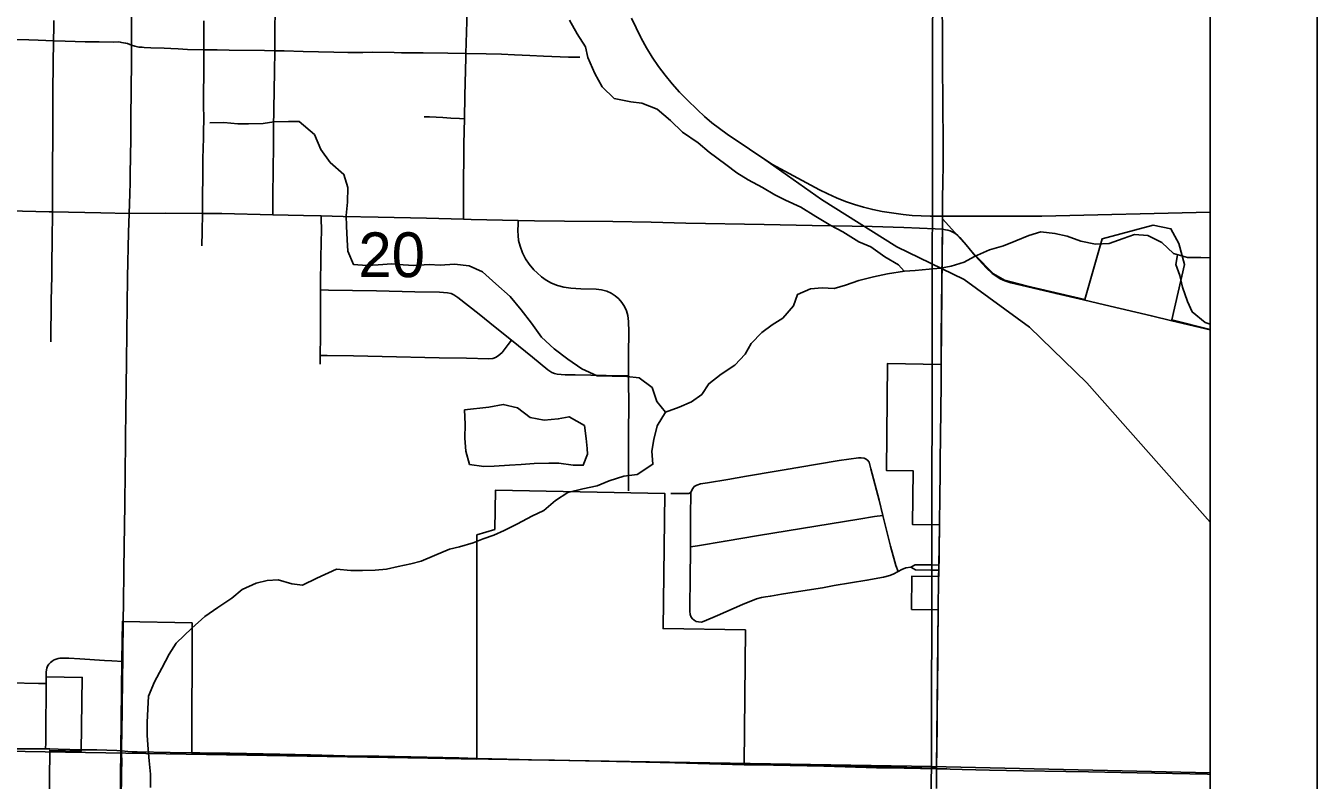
# Model space of a CAD drawing. Extents: x 0 to 34, y 0 to 22.
# Drawn here: x 7.793 to 9, y 18.41 to 19.115 of the extents above; entities that cross this region are included whole.
import ezdxf

# ---------------------------------------------------------------- set-up
doc = ezdxf.new("R2010")
doc.units = 0
for name, color, linetype in [('GM_X_City_Street', 7, 'Continuous'), ('GM_X_County_Road', 7, 'Continuous'), ('GM_X_County_Text', 7, 'Continuous'), ('GM_X_Minor_Lake', 7, 'Continuous'), ('GM_X_Minor_River', 7, 'Continuous'), ('GM_X_Rail_Line', 7, 'Continuous'), ('GM_X_Rail_Line_Text', 7, 'Continuous'), ('GM_X_Section', 7, 'Continuous'), ('GM_X_Section_Text', 7, 'Continuous'), ('GM_X_State_Route', 7, 'Continuous'), ('GM_X_Township_Road', 7, 'Continuous'), ('GM_X_US_Route', 7, 'Continuous'), ('SH_Cut_Line', 7, 'Continuous'), ('SH_Data', 7, 'Continuous')]:
    doc.layers.add(name, color=color, linetype=linetype)

msp = doc.modelspace()

# ---------------------------------------------------------------- linework, layer by layer
at = {"layer": 'GM_X_City_Street'}
for points in [[(8.0237, 18.9388), (8.0237, 18.9421), (8.0237, 18.9557), (8.024, 18.9818), (8.0242, 19.0022), (8.0244, 19.0201), (8.0253, 19.0728), (8.0254, 19.0922), (8.0254, 19.0969), (8.0256, 19.1112), (8.0259, 19.1303)], [(7.816, 18.8201), (7.8165, 18.859), (7.8169, 18.881), (7.817, 18.8932), (7.8174, 18.9149), (7.8175, 18.9415), (7.8175, 18.9544), (7.8177, 18.9892), (7.8178, 19.0065), (7.8178, 19.0187), (7.8179, 19.034), (7.8179, 19.0408), (7.8179, 19.0569), (7.8181, 19.0643), (7.8182, 19.0696), (7.8183, 19.0819), (7.8186, 19.0996), (7.8186, 19.1016), (7.8188, 19.1143), (7.8189, 19.1204)], [(7.9573, 18.9098), (7.9576, 18.9231), (7.958, 18.9401), (7.9582, 18.9909), (7.9585, 19.0014), (7.9587, 19.0101), (7.9588, 19.0113), (7.9588, 19.0151), (7.9589, 19.0181), (7.9591, 19.0268), (7.9589, 19.0436), (7.9588, 19.0479), (7.9588, 19.0522), (7.9589, 19.0552), (7.9589, 19.0583), (7.9591, 19.0645), (7.9591, 19.0695), (7.9592, 19.08), (7.9591, 19.09), (7.9591, 19.0924), (7.9591, 19.0931), (7.9591, 19.0974), (7.9591, 19.106), (7.9591, 19.1084), (7.9591, 19.1202)], [(7.7744, 19.1026), (7.7955, 19.1023), (7.8042, 19.1021), (7.8186, 19.1016), (7.8296, 19.1012), (7.8481, 19.1004), (7.8612, 19.1004), (7.8742, 19.1003), (7.8792, 19.1004), (7.8809, 19.1003), (7.8822, 19.1), (7.8839, 19.0997), (7.886, 19.0993), (7.8878, 19.0988), (7.8916, 19.0975)], [(7.8916, 19.0975), (7.8947, 19.0966), (7.897, 19.0959), (7.8985, 19.0956), (7.8998, 19.0954), (7.9014, 19.0954), (7.9032, 19.0953), (7.9097, 19.095), (7.9219, 19.0946), (7.9284, 19.0942), (7.935, 19.0939), (7.9439, 19.0935), (7.9591, 19.0931), (7.9618, 19.093), (7.9717, 19.093), (7.9828, 19.0928), (8.0157, 19.0924), (8.0254, 19.0922), (8.0342, 19.0921), (8.0521, 19.0915), (8.0806, 19.0907), (8.0936, 19.0906), (8.1079, 19.0906), (8.1172, 19.0907), (8.137, 19.0904), (8.1438, 19.0903), (8.1568, 19.0902), (8.1643, 19.0901), (8.1872, 19.09), (8.2041, 19.0897), (8.2231, 19.0893), (8.2373, 19.089), (8.2496, 19.0883), (8.2638, 19.0878), (8.2768, 19.0872), (8.2922, 19.0866), (8.3, 19.0862), (8.3027, 19.0861), (8.3108, 19.0862)], [(8.165, 19.0305), (8.1702, 19.0303), (8.1827, 19.0297), (8.1901, 19.0292), (8.1981, 19.0288), (8.2027, 19.0286)], [(8.0679, 18.7992), (8.068, 18.8074), (8.0681, 18.8252), (8.0682, 18.8686), (8.0682, 18.8731), (8.0685, 18.8993), (8.069, 18.9254), (8.0689, 18.9343), (8.0689, 18.9377)], [(8.3563, 18.6806), (8.3563, 18.6917), (8.3562, 18.7265), (8.3563, 18.7395), (8.3564, 18.7569), (8.3562, 18.7883), (8.3562, 18.7917), (8.3563, 18.8084), (8.3564, 18.8295), (8.3563, 18.8389), (8.3555, 18.8446), (8.3543, 18.8489), (8.3524, 18.853), (8.35, 18.8568), (8.347, 18.8602), (8.3437, 18.8632), (8.3399, 18.8656), (8.3358, 18.8674), (8.3309, 18.8686), (8.3258, 18.8692), (8.3115, 18.8696), (8.3023, 18.8701), (8.2957, 18.8712), (8.2898, 18.8728), (8.2841, 18.875), (8.2793, 18.8776), (8.2748, 18.8808), (8.2707, 18.8844), (8.2676, 18.8874), (8.2634, 18.8926), (8.26, 18.8977), (8.2572, 18.9031), (8.2548, 18.9094), (8.2534, 18.9147), (8.2529, 18.9195), (8.2528, 18.9238), (8.253, 18.9305), (8.253, 18.9336)], [(8.0682, 18.8686), (8.0757, 18.8684), (8.1205, 18.8676), (8.1565, 18.8668), (8.1795, 18.8664), (8.1868, 18.8658), (8.1903, 18.8651), (8.193, 18.8639), (8.1965, 18.8616), (8.2164, 18.8458), (8.2314, 18.8338), (8.2467, 18.8215), (8.2663, 18.8058), (8.2808, 18.794), (8.2845, 18.7915), (8.2869, 18.7904), (8.2895, 18.7898), (8.297, 18.7893), (8.3064, 18.7892), (8.3498, 18.7884), (8.3562, 18.7883)], [(8.068, 18.8074), (8.0743, 18.8073), (8.0991, 18.8068), (8.1258, 18.8064), (8.1792, 18.8051), (8.2047, 18.8047), (8.2257, 18.8041), (8.2292, 18.8044), (8.2319, 18.8053), (8.2343, 18.8069), (8.2379, 18.8102), (8.2418, 18.8149), (8.2436, 18.8174), (8.2467, 18.8215)], [(8.3957, 18.6784), (8.4045, 18.6783), (8.4098, 18.6783), (8.4124, 18.6784), (8.4143, 18.6791), (8.4151, 18.6808), (8.4162, 18.6829), (8.4176, 18.6848), (8.4199, 18.6859), (8.4235, 18.6873), (8.43, 18.6882), (8.4489, 18.6914), (8.4666, 18.6946), (8.4942, 18.6992), (8.5053, 18.7011), (8.5145, 18.7024), (8.5532, 18.709), (8.5712, 18.7116), (8.5737, 18.7117), (8.5764, 18.7114), (8.5784, 18.7105)], [(8.6082, 18.6052), (8.6062, 18.6109), (8.605, 18.6143), (8.6011, 18.629), (8.594, 18.6577), (8.5905, 18.6719), (8.5826, 18.7014), (8.581, 18.7074), (8.5797, 18.7093), (8.5784, 18.7105)], [(8.4194, 18.5587), (8.4175, 18.5597), (8.4159, 18.5611), (8.4147, 18.5627), (8.4137, 18.5652), (8.4135, 18.5682), (8.4136, 18.5751), (8.4137, 18.5964), (8.414, 18.6283), (8.4142, 18.6599), (8.4145, 18.676), (8.4143, 18.6791)], [(8.414, 18.6283), (8.4206, 18.6294), (8.4464, 18.6337), (8.4777, 18.6389), (8.5715, 18.6544), (8.5862, 18.6566), (8.594, 18.6577)], [(8.4194, 18.5587), (8.4217, 18.5582), (8.4243, 18.5581), (8.4268, 18.5589), (8.4394, 18.5643), (8.4628, 18.5744), (8.4759, 18.5798), (8.4806, 18.5809), (8.4841, 18.5816), (8.4888, 18.5824), (8.4991, 18.5841), (8.5111, 18.5861), (8.5375, 18.5902), (8.5485, 18.5922), (8.5791, 18.5971), (8.5945, 18.5999), (8.6006, 18.6015), (8.6041, 18.603), (8.6075, 18.6049), (8.6082, 18.6052), (8.6118, 18.6072), (8.6153, 18.6086), (8.62, 18.6093)], [(8.62, 18.6093), (8.6243, 18.6116), (8.6255, 18.6117), (8.639, 18.6114), (8.6463, 18.6112)], [(8.62, 18.6093), (8.6244, 18.607), (8.6389, 18.6067), (8.6462, 18.6065)]]:
    msp.add_lwpolyline(points, dxfattribs=at)
at = {"layer": 'GM_X_County_Road'}
for p, q in [((8.6496, 18.9255), (8.6497, 18.9335)), ((8.864, 18.8398), (8.9, 18.8312)), ((8.6484, 18.7872), (8.6484, 18.7969)), ((8.6456, 18.5684), (8.6461, 18.5997))]:
    msp.add_line(p, q, dxfattribs=at)
for points in [[(8.2041, 19.0897), (8.2049, 19.1196), (8.2052, 19.1414), (8.2061, 19.1776)], [(8.6497, 18.9335), (8.6498, 18.9455), (8.6498, 18.9556), (8.6499, 18.9676), (8.6502, 18.9866), (8.6503, 19.0082), (8.65, 19.0399), (8.6499, 19.0548), (8.6498, 19.0679), (8.6497, 19.0896), (8.6496, 19.1108), (8.6494, 19.1319), (8.6491, 19.1605), (8.6491, 19.1611)], [(8.2027, 19.0286), (8.203, 19.05), (8.204, 19.086), (8.2041, 19.0897)], [(8.2019, 18.9347), (8.2019, 18.9371), (8.2019, 18.9414), (8.2018, 18.9468), (8.2019, 18.958), (8.2023, 19.0053), (8.2027, 19.0286)], [(7.7516, 18.9431), (7.8146, 18.9416), (7.8175, 18.9415)], [(7.8175, 18.9415), (7.8628, 18.9405), (7.8892, 18.94)], [(7.8892, 18.94), (7.9231, 18.9403), (7.958, 18.9401)], [(7.958, 18.9401), (7.976, 18.9399), (8.0237, 18.9388)], [(8.0237, 18.9388), (8.0522, 18.9381), (8.0689, 18.9377)], [(8.0689, 18.9377), (8.0895, 18.9371), (8.1221, 18.9365), (8.1672, 18.9356), (8.2019, 18.9347)], [(8.2019, 18.9347), (8.2092, 18.9345), (8.253, 18.9336)], [(8.253, 18.9336), (8.2683, 18.9333), (8.2963, 18.9327), (8.3414, 18.9325), (8.3772, 18.9318), (8.4098, 18.931), (8.4829, 18.9298), (8.528, 18.9288), (8.5653, 18.9281), (8.584, 18.9279), (8.6135, 18.9268), (8.6429, 18.9257), (8.6496, 18.9255)], [(8.6492, 18.8853), (8.6493, 18.8961), (8.6496, 18.9255)], [(8.6496, 18.9255), (8.6525, 18.9249), (8.6546, 18.9244), (8.657, 18.9237), (8.6587, 18.923), (8.6605, 18.922), (8.6622, 18.9209), (8.664, 18.9193), (8.6658, 18.9175), (8.6719, 18.9107), (8.6804, 18.9004)], [(8.6804, 18.9004), (8.6905, 18.8892), (8.6962, 18.884), (8.6998, 18.8813), (8.7037, 18.879), (8.7079, 18.8771), (8.7137, 18.8752), (8.7559, 18.8652), (8.7815, 18.8592)], [(8.6484, 18.7969), (8.6484, 18.7979), (8.6484, 18.8044), (8.6486, 18.8296), (8.6487, 18.8458), (8.6489, 18.8551), (8.6491, 18.8744), (8.6492, 18.8853)], [(8.7815, 18.8592), (8.8012, 18.8546), (8.845, 18.8442), (8.864, 18.8398)], [(8.6469, 18.647), (8.6469, 18.648), (8.6472, 18.6774), (8.6474, 18.6951), (8.6476, 18.7084), (8.6481, 18.7555), (8.6484, 18.7813), (8.6484, 18.7872)], [(8.6462, 18.6065), (8.6463, 18.6112), (8.6469, 18.647)], [(8.6461, 18.5997), (8.6461, 18.6021), (8.6462, 18.6065)], [(8.6441, 18.4208), (8.6444, 18.4408), (8.6446, 18.4595), (8.6446, 18.4713), (8.6453, 18.526), (8.6453, 18.5391), (8.6456, 18.5684)], [(8.6441, 18.4023), (8.6441, 18.4208)]]:
    msp.add_lwpolyline(points, dxfattribs=at)
at = {"layer": 'GM_X_County_Text'}
msp.add_lwpolyline([(8.9, 16.3981), (8.9, 20.9)], dxfattribs=at)
at = {"layer": 'GM_X_Minor_Lake'}
for points in [[(8.3174, 18.7203), (8.3166, 18.7296), (8.3149, 18.7418), (8.3006, 18.75), (8.2904, 18.7479), (8.2774, 18.7467), (8.2642, 18.7492), (8.2523, 18.7582), (8.2391, 18.7615), (8.2257, 18.7591), (8.2029, 18.7565)], [(8.2029, 18.7565), (8.2034, 18.7432), (8.2032, 18.7299), (8.2041, 18.7177), (8.2076, 18.7055), (8.2209, 18.7034), (8.2307, 18.7039), (8.2448, 18.7048), (8.2558, 18.7053), (8.2679, 18.7062), (8.2816, 18.7067), (8.2911, 18.7066), (8.3043, 18.7048), (8.3138, 18.7046), (8.3178, 18.7151), (8.3174, 18.7203)]]:
    msp.add_lwpolyline(points, dxfattribs=at)
at = {"layer": 'GM_X_Minor_River'}
for points in [[(8.6138, 18.8861), (8.6087, 18.892), (8.5959, 18.8995), (8.5828, 18.9088), (8.5715, 18.9136), (8.5565, 18.923), (8.5453, 18.9289), (8.5314, 18.9371), (8.5172, 18.9458), (8.5029, 18.9525), (8.4931, 18.9576), (8.4815, 18.9643), (8.468, 18.9714), (8.4575, 18.978), (8.447, 18.9858), (8.4317, 18.9975), (8.4213, 19.0061), (8.4067, 19.0162), (8.3955, 19.0271), (8.3828, 19.0376), (8.3685, 19.0431), (8.3583, 19.0445), (8.3428, 19.0474), (8.3316, 19.0583), (8.3247, 19.0709), (8.3181, 19.0859), (8.316, 19.0958), (8.3083, 19.1081), (8.301, 19.1207)], [(8.3906, 18.7543), (8.3825, 18.7643), (8.3782, 18.7773), (8.3662, 18.7863), (8.3545, 18.7877), (8.3268, 18.7882), (8.3125, 18.7949), (8.2994, 18.8039), (8.2867, 18.8136), (8.2748, 18.8245), (8.2656, 18.8376), (8.2559, 18.8499), (8.2456, 18.8623), (8.2321, 18.8743), (8.2198, 18.8855), (8.2071, 18.8911), (8.1934, 18.8925), (8.1801, 18.8916), (8.1699, 18.8922), (8.1555, 18.8913), (8.1456, 18.8919), (8.135, 18.8929), (8.1221, 18.892), (8.1115, 18.8914), (8.099, 18.8924), (8.0939, 18.9047), (8.093, 18.9153), (8.0925, 18.9282), (8.0923, 18.9381), (8.0933, 18.9506), (8.0939, 18.9643), (8.09, 18.9765), (8.0773, 18.9877), (8.0685, 18.9997), (8.0627, 19.0138), (8.0481, 19.0259), (8.0383, 19.0261), (8.0246, 19.0256), (8.0147, 19.0242), (8.001, 19.0237), (7.9908, 19.0239), (7.9779, 19.025), (7.9647, 19.0248)], [(8.9, 18.8986), (8.8913, 18.899), (8.8788, 18.8989), (8.8656, 18.9026), (8.8548, 18.913), (8.8416, 18.9193), (8.8291, 18.9203), (8.8185, 18.9168), (8.8055, 18.9121), (8.7929, 18.9112), (8.779, 18.9141), (8.7662, 18.9189), (8.7548, 18.9214), (8.7416, 18.9228), (8.7305, 18.9196), (8.7183, 18.9145), (8.7068, 18.9098), (8.6935, 18.9059), (8.6797, 18.8997), (8.6701, 18.8946), (8.6579, 18.8907), (8.6477, 18.889), (8.6374, 18.888), (8.6241, 18.8868), (8.6142, 18.8862), (8.5983, 18.8835), (8.5853, 18.8807), (8.5716, 18.8775), (8.559, 18.8729), (8.5483, 18.87), (8.5373, 18.8706), (8.5263, 18.8697), (8.5141, 18.8642), (8.5105, 18.8537), (8.5004, 18.8421), (8.4904, 18.8359), (8.4808, 18.8288), (8.4707, 18.8184)], [(8.8693, 18.9015), (8.868, 18.8923), (8.8716, 18.882), (8.8741, 18.8713), (8.8788, 18.8579), (8.8831, 18.848), (8.8954, 18.8382), (8.9, 18.8366)], [(8.4707, 18.8184), (8.4652, 18.8086), (8.4555, 18.7982), (8.4429, 18.7897), (8.4313, 18.7808), (8.4247, 18.7707), (8.4151, 18.7641), (8.4036, 18.759), (8.3906, 18.7543), (8.3828, 18.7416), (8.3799, 18.7287), (8.3781, 18.7178), (8.379, 18.7056), (8.3644, 18.696), (8.3519, 18.6944), (8.3382, 18.6901), (8.3267, 18.6854), (8.3134, 18.6826), (8.2993, 18.6791), (8.2878, 18.6717), (8.277, 18.6624), (8.2659, 18.657), (8.2524, 18.65), (8.2398, 18.6438), (8.2303, 18.6394), (8.2203, 18.6358), (8.2108, 18.6322), (8.1982, 18.6283), (8.1887, 18.6262), (8.1749, 18.6204), (8.1623, 18.615), (8.1527, 18.6125), (8.1409, 18.6101), (8.1299, 18.6076), (8.1193, 18.6067), (8.1075, 18.6062), (8.0965, 18.6064), (8.0833, 18.6074), (8.0649, 18.599), (8.0515, 18.5925), (8.0413, 18.5938), (8.0285, 18.5975), (8.0182, 18.5969), (8.0079, 18.5945), (7.9949, 18.5886), (7.9853, 18.5805), (7.9722, 18.5716), (7.9599, 18.5631), (7.948, 18.5524), (7.9333, 18.5382), (7.9266, 18.5281), (7.9199, 18.515), (7.9129, 18.5022), (7.9073, 18.4887), (7.9067, 18.4769), (7.906, 18.464), (7.9062, 18.4519), (7.9071, 18.4393), (7.908, 18.4283), (7.9093, 18.4158), (7.9094, 18.4033)]]:
    msp.add_lwpolyline(points, dxfattribs=at)
at = {"layer": 'GM_X_Rail_Line'}
for points in [[(8.3591, 19.1227), (8.3632, 19.1135), (8.3677, 19.1045), (8.3679, 19.104), (8.3729, 19.0949), (8.3783, 19.0861), (8.3841, 19.0775), (8.3903, 19.0692), (8.3969, 19.0612), (8.4038, 19.0535), (8.411, 19.0462), (8.4206, 19.0369), (8.4272, 19.0307), (8.434, 19.0249), (8.4412, 19.0194), (8.4485, 19.0142), (8.4901, 18.9861), (8.5347, 18.9623), (8.5426, 18.9583), (8.5507, 18.9546), (8.559, 18.9513), (8.5674, 18.9484), (8.5759, 18.9459), (8.5845, 18.9437), (8.5932, 18.942), (8.6019, 18.9406), (8.6129, 18.9392), (8.6214, 18.9382), (8.6298, 18.9377), (8.6383, 18.9375), (8.7426, 18.9375), (8.9, 18.9412)], [(8.9, 18.6514), (8.7847, 18.7817), (8.7311, 18.8338), (8.6699, 18.8782), (8.6071, 18.9088), (8.5367, 18.9532), (8.4836, 18.9905)]]:
    msp.add_lwpolyline(points, dxfattribs=at)
at = {"layer": 'GM_X_Rail_Line_Text'}
for points in [[(8.9, 18.4172), (8.9, 19.4179), (8.641, 19.4232), (8.6393, 18.4229)], [(8.9, 17.4062), (8.9, 18.4172), (8.6393, 18.4229), (8.6173, 17.4112)]]:
    msp.add_lwpolyline(points, close=True, dxfattribs=at)
at = {"layer": 'GM_X_Section'}
for points in [[(7.6399, 19.4548), (8.641, 19.4232), (8.6393, 18.4229), (7.6223, 18.4397)], [(7.6223, 18.4397), (8.6393, 18.4229), (8.6173, 17.4112), (7.606, 17.4298)]]:
    msp.add_lwpolyline(points, close=True, dxfattribs=at)
at = {"layer": 'GM_X_State_Route'}
msp.add_line((7.8817, 18.3877), (7.8822, 18.4203), dxfattribs=at)
for points in [[(7.8916, 19.0975), (7.8916, 19.1093), (7.8916, 19.1349), (7.8918, 19.1715), (7.892, 19.1855)], [(7.8901, 18.9691), (7.8902, 18.9711), (7.8904, 18.9801), (7.8905, 18.9899), (7.8908, 19.0131), (7.8909, 19.0248), (7.891, 19.0388), (7.8911, 19.0461), (7.8912, 19.0631), (7.8914, 19.0745), (7.8915, 19.0919), (7.8916, 19.0975)], [(7.8892, 18.94), (7.8898, 18.9585), (7.8901, 18.9691)], [(7.8862, 18.7542), (7.8869, 18.802), (7.8879, 18.8805), (7.8887, 18.9222), (7.8892, 18.94)], [(7.8853, 18.6738), (7.8856, 18.6927), (7.8859, 18.7312), (7.8862, 18.7542)], [(7.885, 18.6455), (7.8851, 18.6465), (7.8852, 18.6698), (7.8853, 18.6738)], [(7.8837, 18.5586), (7.884, 18.5771), (7.8844, 18.6043), (7.8847, 18.6316), (7.885, 18.6455)], [(7.8833, 18.5213), (7.8833, 18.5291), (7.8837, 18.5577), (7.8837, 18.5586)], [(7.8822, 18.4377), (7.8822, 18.4396), (7.8827, 18.4744), (7.8831, 18.5079), (7.8833, 18.5213)], [(7.8822, 18.4203), (7.8823, 18.4253), (7.8822, 18.4377)]]:
    msp.add_lwpolyline(points, dxfattribs=at)
at = {"layer": 'GM_X_Township_Road'}
msp.add_line((7.8112, 18.4394), (7.8152, 18.4394), dxfattribs=at)
for points in [[(7.8116, 18.4998), (7.8116, 18.5111), (7.8119, 18.5135), (7.8122, 18.5148), (7.8126, 18.5159), (7.813, 18.5167), (7.8135, 18.5176), (7.8142, 18.5186), (7.815, 18.5195), (7.8157, 18.5202), (7.8169, 18.5211)], [(7.8169, 18.5211), (7.8187, 18.5223), (7.82, 18.5229), (7.8211, 18.5234), (7.8221, 18.5238), (7.8229, 18.524), (7.8244, 18.5242), (7.8266, 18.5243), (7.8328, 18.5243), (7.8433, 18.5238), (7.8662, 18.5221), (7.873, 18.5218), (7.8833, 18.5213)], [(7.8112, 18.4394), (7.8113, 18.4452), (7.8113, 18.4627), (7.8116, 18.4914), (7.8116, 18.4998)], [(7.75, 18.4398), (7.7836, 18.4395), (7.8112, 18.4394)], [(7.8152, 18.4394), (7.823, 18.4393), (7.8446, 18.4387), (7.8455, 18.4387)], [(7.8455, 18.4387), (7.8517, 18.4386), (7.8592, 18.4385), (7.8777, 18.4379), (7.8822, 18.4377)], [(7.8822, 18.4377), (7.888, 18.4371), (7.8922, 18.4368), (7.8967, 18.4366), (7.9277, 18.4361), (7.9479, 18.4359)], [(7.9479, 18.4359), (7.9554, 18.4357), (7.9834, 18.4354), (8.0301, 18.4345), (8.0587, 18.4339), (8.0908, 18.4331), (8.1227, 18.4326), (8.1975, 18.431), (8.2146, 18.4305)], [(8.2146, 18.4305), (8.2424, 18.4298), (8.2654, 18.4294), (8.2871, 18.4288), (8.3449, 18.4278), (8.3996, 18.4264), (8.4642, 18.4246)], [(8.4642, 18.4246), (8.4917, 18.4243), (8.5388, 18.4232), (8.5587, 18.4227), (8.5879, 18.4219), (8.614, 18.4216), (8.6441, 18.4208)], [(8.6441, 18.4208), (8.6539, 18.4207), (8.657, 18.4206), (8.6682, 18.4203), (8.6937, 18.4197), (8.7254, 18.4191), (8.7651, 18.4184), (8.7863, 18.418), (8.8317, 18.4171), (8.8976, 18.4157), (8.9, 18.4156)]]:
    msp.add_lwpolyline(points, dxfattribs=at)
at = {"layer": 'GM_X_US_Route'}
msp.add_line((7.8817, 18.3877), (7.8822, 18.4203), dxfattribs=at)
for points in [[(7.8808, 18.3885), (7.8814, 18.4385), (7.8825, 18.5221), (7.883, 18.5586), (7.9482, 18.5572), (7.948, 18.4354), (8.2145, 18.43), (8.2145, 18.6395), (8.2311, 18.6446), (8.2318, 18.6813), (8.3901, 18.6783), (8.3885, 18.552), (8.4655, 18.5507), (8.4642, 18.4254), (8.6441, 18.4215), (8.6458, 18.5694), (8.6208, 18.5698), (8.6211, 18.6011), (8.6462, 18.6006), (8.6468, 18.6488), (8.6217, 18.6492), (8.6223, 18.6993), (8.5973, 18.6999), (8.5984, 18.7999), (8.6484, 18.7987), (8.6498, 18.9349), (8.6613, 18.9222), (8.6801, 18.901), (8.6973, 18.8836), (8.7078, 18.8778), (8.728, 18.8725), (8.7829, 18.8596), (8.7991, 18.9164), (8.8466, 18.929), (8.8633, 18.9257), (8.8707, 18.9121), (8.876, 18.8924), (8.864, 18.8405), (8.9, 18.8317), (8.9, 19.8361)], [(7.8916, 19.0975), (7.8916, 19.1093), (7.8916, 19.1349), (7.8918, 19.1715), (7.892, 19.1855)], [(7.8901, 18.9691), (7.8902, 18.9711), (7.8904, 18.9801), (7.8905, 18.9899), (7.8908, 19.0131), (7.8909, 19.0248), (7.891, 19.0388), (7.8911, 19.0461), (7.8912, 19.0631), (7.8914, 19.0745), (7.8915, 19.0919), (7.8916, 19.0975)], [(7.8892, 18.94), (7.8898, 18.9585), (7.8901, 18.9691)], [(7.8862, 18.7542), (7.8869, 18.802), (7.8879, 18.8805), (7.8887, 18.9222), (7.8892, 18.94)], [(7.8853, 18.6738), (7.8856, 18.6927), (7.8859, 18.7312), (7.8862, 18.7542)], [(7.885, 18.6455), (7.8851, 18.6465), (7.8852, 18.6698), (7.8853, 18.6738)], [(7.8837, 18.5586), (7.884, 18.5771), (7.8844, 18.6043), (7.8847, 18.6316), (7.885, 18.6455)], [(7.8833, 18.5213), (7.8833, 18.5291), (7.8837, 18.5577), (7.8837, 18.5586)], [(7.1266, 18.4421), (7.16, 18.442), (7.2067, 18.4419), (7.2347, 18.4419), (7.3201, 18.4414), (7.5246, 18.4414), (7.5642, 18.4414), (7.7499, 18.4391), (7.7512, 18.5206), (7.7784, 18.5201), (7.7782, 18.5012), (7.8045, 18.5007), (7.8117, 18.5006), (7.8118, 18.5069), (7.8454, 18.5063), (7.8445, 18.4374), (7.815, 18.438), (7.8144, 18.3839)], [(7.8822, 18.4377), (7.8822, 18.4396), (7.8827, 18.4744), (7.8831, 18.5079), (7.8833, 18.5213)], [(7.8822, 18.4203), (7.8823, 18.4253), (7.8822, 18.4377)]]:
    msp.add_lwpolyline(points, dxfattribs=at)
at = {"layer": 'SH_Cut_Line'}
msp.add_lwpolyline([(8.9, 16.3981), (8.9, 20.9), (2.1, 20.9)], dxfattribs=at)
at = {"layer": 'SH_Data'}
for p, q in [((9, 21), (9, 14)), ((8.9, 20.9), (8.9, 14.1))]:
    msp.add_line(p, q, dxfattribs=at)

# ---------------------------------------------------------------- texts
at = {"layer": 'GM_X_Section_Text'}
msp.add_text('20', height=0.04186, rotation=0, dxfattribs=at).set_placement((8.1036, 18.8805))

doc.saveas('drawing.dxf')
